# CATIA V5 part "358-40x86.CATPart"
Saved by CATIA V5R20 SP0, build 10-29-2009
Part number: 358-40X86
Definition: NONE
Nomenclature: 358-40X86
Source: Unknown
Description: 358-40X86
Bounding box of the stored display mesh (mm): x -18 to 68, y -26 to 26, z -26 to 26
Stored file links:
  C:\Users\Utente\Desktop\IO LAVORO\3D X SITO CF\X SITO\PLASTICA\358\358-40x86.CATPart
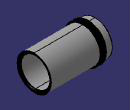
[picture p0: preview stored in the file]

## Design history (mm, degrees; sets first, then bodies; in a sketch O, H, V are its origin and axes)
Body1 "358-40X86" (main body)
  Solid1: solid without history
